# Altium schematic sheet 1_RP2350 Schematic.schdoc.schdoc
size 431 x 309 mm; Symbol: Sheet layout Github; Device: Sheet layout Github; @Project Name: RP2350; @Page Name: RP2350 Schematic.RP2350 Dev Board; Part Number: JLCPCB-002; Drawn: EasyEDA; @Page Count: 1; @Update Date: 2024-10-01; @Create Date: 2024-10-01; @Schematic Name: RP2350 Dev Board; @Page No: 1; Company: github.com/Gokul-Kannan-04; Reviewed: Gokul-Kannan-04; Version: V0.1; Page Size: A4
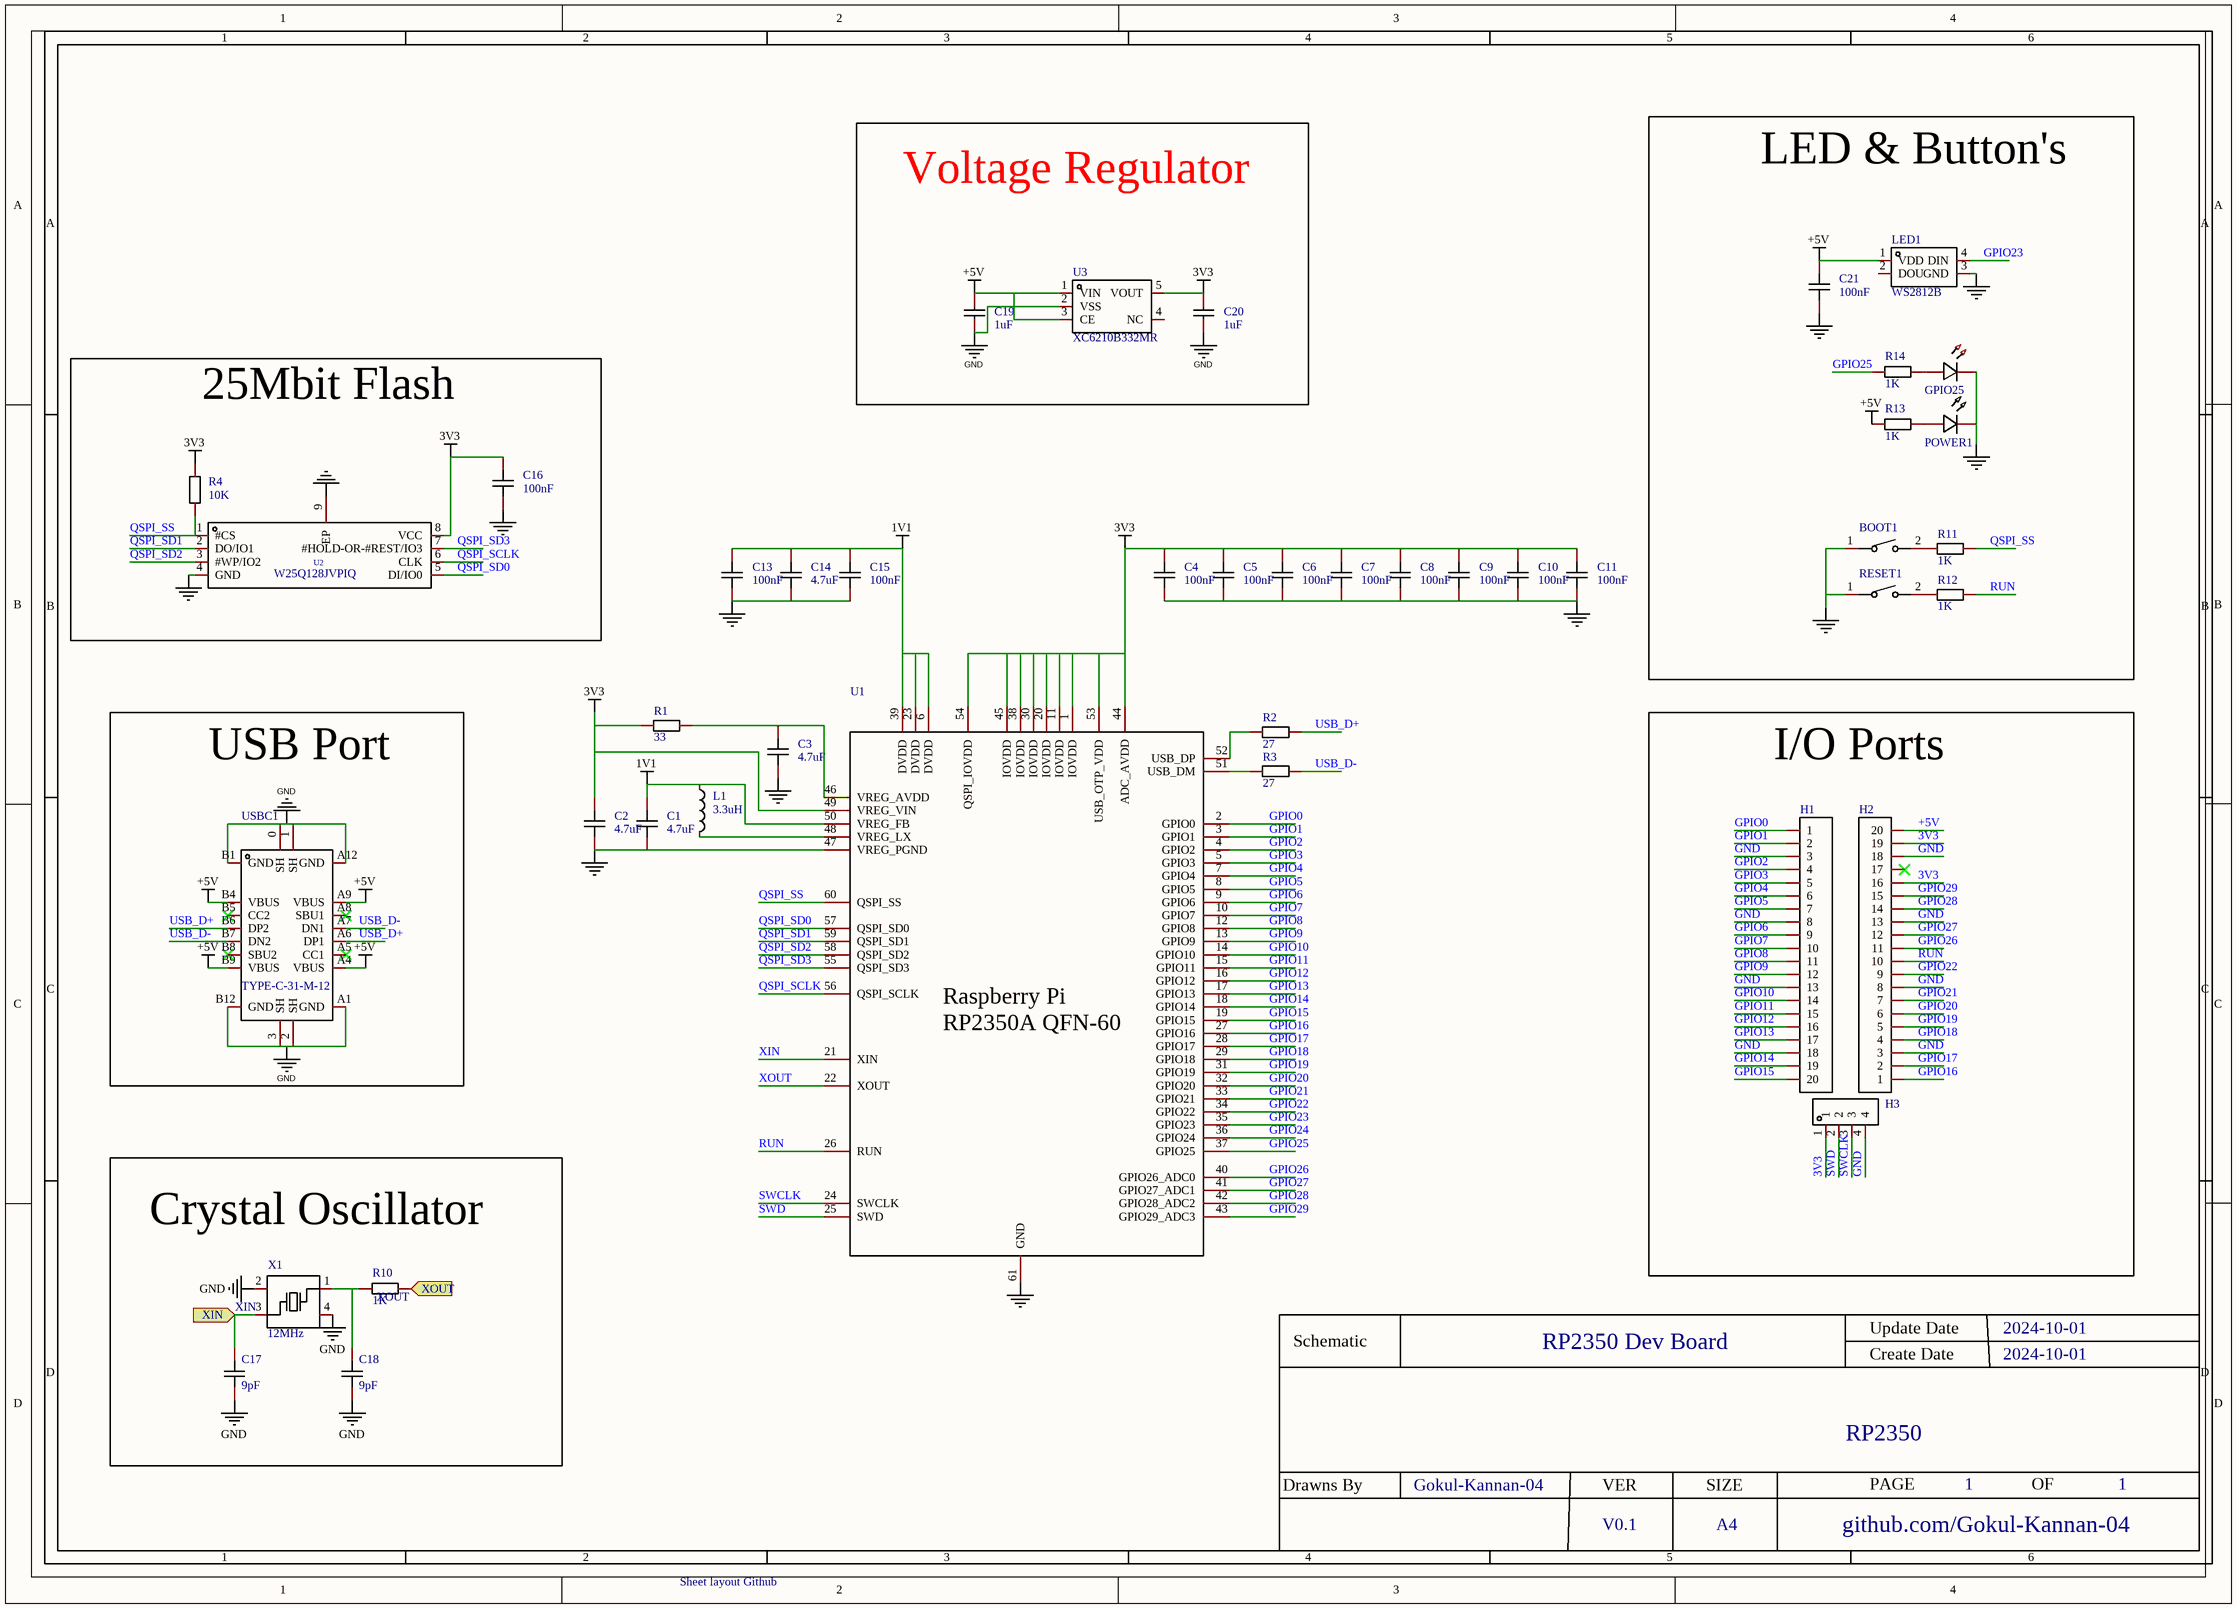
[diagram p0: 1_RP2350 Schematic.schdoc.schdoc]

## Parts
BOOT1  TS-1088-AR02016  [SW-SMD_L3.9-W3.0-P4.45]  (value not drawn)
C1  4.7uF  [C0402]
C2  4.7uF  [C0402]
C3  4.7uF  [C0402]
C4  100nF  [C0402]
C5  100nF  [C0402]
C6  100nF  [C0402]
C7  100nF  [C0402]
C8  100nF  [C0402]
C9  100nF  [C0402]
C10  100nF  [C0402]
C11  100nF  [C0402]
C13  100nF  [C0402]
C14  4.7uF  [C0402]
C15  100nF  [C0402]
C16  100nF  [C0402]
C17  value 9pF  [C0402]  (hidden comment: CAP_0402)
C18  value 9pF  [C0402]  (hidden comment: CAP_0402)
C19  1uF  [C0603]
C20  1uF  [C0603]
C21  100nF  [C0402]
GPIO25  LED_0402-G  [LED_0402]  (value not drawn)
H1  HDR-F_2.54_1x20P  [HDR-TH_20P-P2.54-V-F]  (value not drawn)
H2  HDR-F_2.54_1x20P  [HDR-TH_20P-P2.54-V-F]  (value not drawn)
H3  HDR-F_2.54_1x4P  [HDR-TH_4P-P2.54-V-F]  (value not drawn)
L1  3.3uH  [IND-SMD_L2.0-W1.6_FTC201610S]
LED1  WS2812B  [LED-SMD_4P-L5.0-W5.0-BL_XL-5050RGBC]
POWER1  LED_0402-R  [LED_0402]  (value not drawn)
R1  33  [R0402]
R2  27  [R0402]
R3  27  [R0402]
R4  10K  [R0402]
R10  value 1K  [R0402]  (hidden comment: Res_0402)
R11  1K  [R0402]
R12  1K  [R0402]
R13  value 1K  [R0402]  (hidden comment: Res_0402)
R14  value 1K  [R0402]  (hidden comment: Res_0402)
RESET1  TS-1088-AR02016  [SW-SMD_L3.9-W3.0-P4.45]  (value not drawn)
U1  RP2350A  [qfn-60_l7.0-w7.0-p0.40-tl-ep4.0]  (value not drawn)
U2  W25Q128JVPIQ  [WSON-8_L6.0-W5.0-P1.27-BL-EP]
U3  XC6210B332MR  [TSOT-23-5_L2.9-W1.6-P0.95-LS2.8-BR]
USBC1  TYPE-C-31-M-12  [USB-C_SMD-TYPE-C-31-M-12]
X1  12MHz  [OSC-SMD_4P-L3.2-W2.5-BL]

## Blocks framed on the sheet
Voltage Regulator: C19 C20 U3
LED & Button's: BOOT1 C21 GPIO25 LED1 POWER1 R11-R14 RESET1
25Mbit Flash: C16 R4 U2
USB Port: USBC1
I/O Ports: H1-H3
Crystal Oscillator: C17 C18 R10 X1

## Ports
XIN (in), XOUT (in)

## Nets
1V1: C1.2 C13.2 C14.2 C15.2 L1.1 U1.6(DVDD) U1.23(DVDD) U1.39(DVDD) U1.50(VREG_FB)
3V3: C2.2 C4.2 C5.2 C6.2 C7.2 C8.2 C9.2 C10.2 C11.2 C16.2 C20.2 H2.16 H2.19 H3.1 R1.1 R4.2 U1.1(IOVDD) U1.11(IOVDD) U1.20(IOVDD) U1.30(IOVDD) U1.38(IOVDD) U1.44(ADC_AVDD) U1.45(IOVDD) U1.49(VREG_VIN) U1.53(USB_OTP_VDD) U1.54(QSPI_IOVDD) U2.8(VCC) U3.5(VOUT)
+5V: C19.2 C21.2 H2.20 LED1.1(VDD) R13.1 U3.1(VIN) U3.3(CE) USBC1.A4(VBUS) USBC1.A9(VBUS) USBC1.B4(VBUS) USBC1.B9(VBUS)
GND: BOOT1.1 C1.1 C2.1 C3.1 C4.1 C5.1 C6.1 C7.1 C8.1 C9.1 C10.1 C11.1 C13.1 C14.1 C15.1 C16.1 C17.1 C18.1 C19.1 C20.1 C21.1 GPIO25.1(C) H1.3 H1.8 H1.13 H1.18 H2.3 H2.8 H2.13 H2.18 H3.4 LED1.3(GND) POWER1.1(C) RESET1.1 U1.47(VREG_PGND) U1.61(GND) U2.4(GND) U2.9(EP) U3.2(VSS) USBC1.0(SH) USBC1.1(SH) USBC1.2(SH) USBC1.3(SH) USBC1.A1(GND) USBC1.A12(GND) USBC1.B1(GND) USBC1.B12(GND) X1.2(GND) X1.4(GND)
GPIO0: H1.1 U1.2(GPIO0)
GPIO1: H1.2 U1.3(GPIO1)
GPIO2: H1.4 U1.4(GPIO2)
GPIO3: H1.5 U1.5(GPIO3)
GPIO4: H1.6 U1.7(GPIO4)
GPIO5: H1.7 U1.8(GPIO5)
GPIO6: H1.9 U1.9(GPIO6)
GPIO7: H1.10 U1.10(GPIO7)
GPIO8: H1.11 U1.12(GPIO8)
GPIO9: H1.12 U1.13(GPIO9)
GPIO10: H1.14 U1.14(GPIO10)
GPIO11: H1.15 U1.15(GPIO11)
GPIO12: H1.16 U1.16(GPIO12)
GPIO13: H1.17 U1.17(GPIO13)
GPIO14: H1.19 U1.18(GPIO14)
GPIO15: H1.20 U1.19(GPIO15)
GPIO16: H2.1 U1.27(GPIO16)
GPIO17: H2.2 U1.28(GPIO17)
GPIO18: H2.4 U1.29(GPIO18)
GPIO19: H2.5 U1.31(GPIO19)
GPIO20: H2.6 U1.32(GPIO20)
GPIO21: H2.7 U1.33(GPIO21)
GPIO22: H2.9 U1.34(GPIO22)
GPIO23: LED1.4(DIN) U1.35(GPIO23)
GPIO24: U1.36(GPIO24)
GPIO25: R14.1 U1.37(GPIO25)
GPIO26: H2.11 U1.40(GPIO26_ADC0)
GPIO27: H2.12 U1.41(GPIO27_ADC1)
GPIO28: H2.14 U1.42(GPIO28_ADC2)
GPIO29: H2.15 U1.43(GPIO29_ADC3)
QSPI_SCLK: U1.56(QSPI_SCLK) U2.6(CLK)
QSPI_SD0: U1.57(QSPI_SD0) U2.5(DI/IO0)
QSPI_SD1: U1.59(QSPI_SD1) U2.2(DO/IO1)
QSPI_SD2: U1.58(QSPI_SD2) U2.3(#WP/IO2)
QSPI_SD3: U1.55(QSPI_SD3) U2.7(#HOLD-OR-#REST/IO3)
QSPI_SS: R4.1 R11.2 U1.60(QSPI_SS) U2.1(#CS)
RUN: H2.10 R12.2 U1.26(RUN)
SWCLK: H3.3 U1.24(SWCLK)
SWD: H3.2 U1.25(SWD)
USB_D+: R2.2 USBC1.A6(DP1) USBC1.B6(DP2)
USB_D-: R3.2 USBC1.A7(DN1) USBC1.B7(DN2)
XIN: C17.2 U1.21(XIN) X1.3(OSC2) ; port XIN
XOUT: R10.2 U1.22(XOUT) ; port XOUT
NetBOOT1_2: BOOT1.2 R11.1
NetC3_2: C3.2 R1.2 U1.46(VREG_AVDD)
NetC18_2: C18.2 R10.1 X1.1(OSC1)
NetGPIO25_2: GPIO25.2(A) R14.2
NetL1_2: L1.2 U1.48(VREG_LX)
NetPOWER1_2: POWER1.2(A) R13.2
NetR2_1: R2.1 U1.52(USB_DP)
NetR3_1: R3.1 U1.51(USB_DM)
NetR12_1: R12.1 RESET1.2

Not connected (* = marked no-connect by the designer): H2 17*; LED1 2(DOU); U3 4(NC); USBC1 A5(CC1)* A8(SBU1)* B5(CC2)* B8(SBU2)*

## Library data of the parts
BOOT1 RESET1 = TS-1088-AR02016: Manufacturer: XUNPU(讯普); Add into BOM: yes; Circuit: 单刀单掷; Actuator Style: 圆形按钮; Operating Force: 160gf; Switch Length: 4mm; Switch Width: 3mm; Switch Height: 2mm; Strike Gundam: 不带; Contact Current: 50mA; Voltage Rating (DC): 12V; Insulation Resistance: 100MΩ; Actuator/Cap Color: 黑色; Pin Style: SMD接片; Mechanical Life: 10万次; Description: 电路结构:单刀单掷;按钮形状:圆形按钮;作用力:160gf;安装方式:立贴;开关长度:4mm;开关宽度:3mm;开关高度:2mm;带支架:不带;触点电流:50mA;额定电压(DC):12V;绝缘电阻:100MΩ;机械寿命:10万次;
C1-C11 C13-C16 C21 = CAP_0402: Symbol: CapAcitance; Convert to PCB: yes
C17 C18 = CAP_0402: Symbol: C1210X7R475K630NT; Convert to PCB: yes; Description: 容值:100nF;精度:±10%;额定电压:16V;温度系数:X7R;
C19 C20 = CL10A105KB8NNNC: Manufacturer: SAMSUNG(三星); Add into BOM: yes; Tolerance: ±10%; Voltage Rated: 50V; Temperature Coefficient: X5R; Description: 容值:1uF;精度:±10%;额定电压:50V;材质(温度系数):X5R;
GPIO25 = LED_0402-G: Symbol: LED_G; Convert to PCB: yes
H1 H2 = HDR-F_2.54_1x20P: Convert to PCB: yes
H3 = HDR-F_2.54_1x4P: Manufacturer: BOOMELE(博穆精密); Symbol: 2.54-1*4P母; Convert to PCB: yes
L1 = FTC201610S3R3MBCA: Manufacturer: cjiang(长江微电); Add into BOM: yes; Tolerance: ±20%; Rated Current: 1.7A; Saturation Current (Isat): 2.3A; DC Resistance (DCR): 140mΩ; Type: 一体成型电感; Description: 电感值:3.3uH;精度:±20%;额定电流:1.7A;饱和电流(Isat):2.3A;类型:一体成型电感;
LED1 = XL-5050RGBC-WS2812B: Manufacturer: XINGLIGHT(成兴光); Add into BOM: yes; Description: 5050七彩幻彩透明贴片LED灯珠 5050 幻彩透明四脚 ws2812B 内置驱动IC
POWER1 = LED_0402-R: Symbol: LED_R; Convert to PCB: yes
R1-R4 R10-R14 = Res_0402: Symbol: 电阻; Convert to PCB: yes
U1 = RP2350A: Add into BOM: yes
U2 = W25Q128JVPIQ_C190862: Manufacturer: WINBOND(华邦); Symbol: W25Q128JVPIQTR; Add into BOM: yes; Memory Size: 128Mbit; Description: 存储容量:128Mbit;
U3 = XC6210B332MR_C424705: Manufacturer: TOREX(特瑞仕); Add into BOM: yes; Output Type: 固定; Maximum Input Voltage: 6V; Output Voltage: 3.3V; MAX Output Current: 900mA; Power Supply Rejection Ratio (PSRR): 60dB@(1kHz); Dropout Voltage: 75mV@(100mA); Output Polarity: 正极; Number of Outputs: 1; Description: 输出类型:固定;最大输入电压:6V;输出电压:3.3V;最大输出电流:900mA;电源纹波抑制比(PSRR):60dB@(1kHz);输出极性:正极;
USBC1 = TYPE-C-31-M-12: Manufacturer: 韩国韩荣; Add into BOM: yes; Connector Type: Type-C; Gender: 母; Number of Ports: 1; Number of Contacts: 16P; Current Rating - Power (Max): 5A; Description: 连接器类型:Type-C;标准:-;公母:母;端口数量:1;触点数量:16P;安装方式:-;额定电流 - 电源:5A;触头材质:-;触头镀层:-;工作温度范围:-;焊接温度(最大值):-;
X1 = X322512MLB4SI: 晶振类型:贴片无源晶振;频率:12MHz;频率公差:±10ppm;频率稳定度:±30ppm;负载电容:9pF;工作温度:-40~+85;; Manufacturer: YXC(扬兴科技); Add into BOM: yes; Crystal Type: 贴片无源晶振; Frequency Tolerance: ±10ppm; Frequency Stability: ±30ppm; Load Capacitance: 9pF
